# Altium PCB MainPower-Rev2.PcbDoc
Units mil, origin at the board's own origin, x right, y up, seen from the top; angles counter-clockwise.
Board outline 11010.03 x 11010.03 mil, 4 copper layers (Top Layer, Internal Plane 1, Internal Plane 2, Bottom Layer); 112 components, 94 nets, 482 pads, 0 vias.
Unrouted connection lines stored in the file: 312.
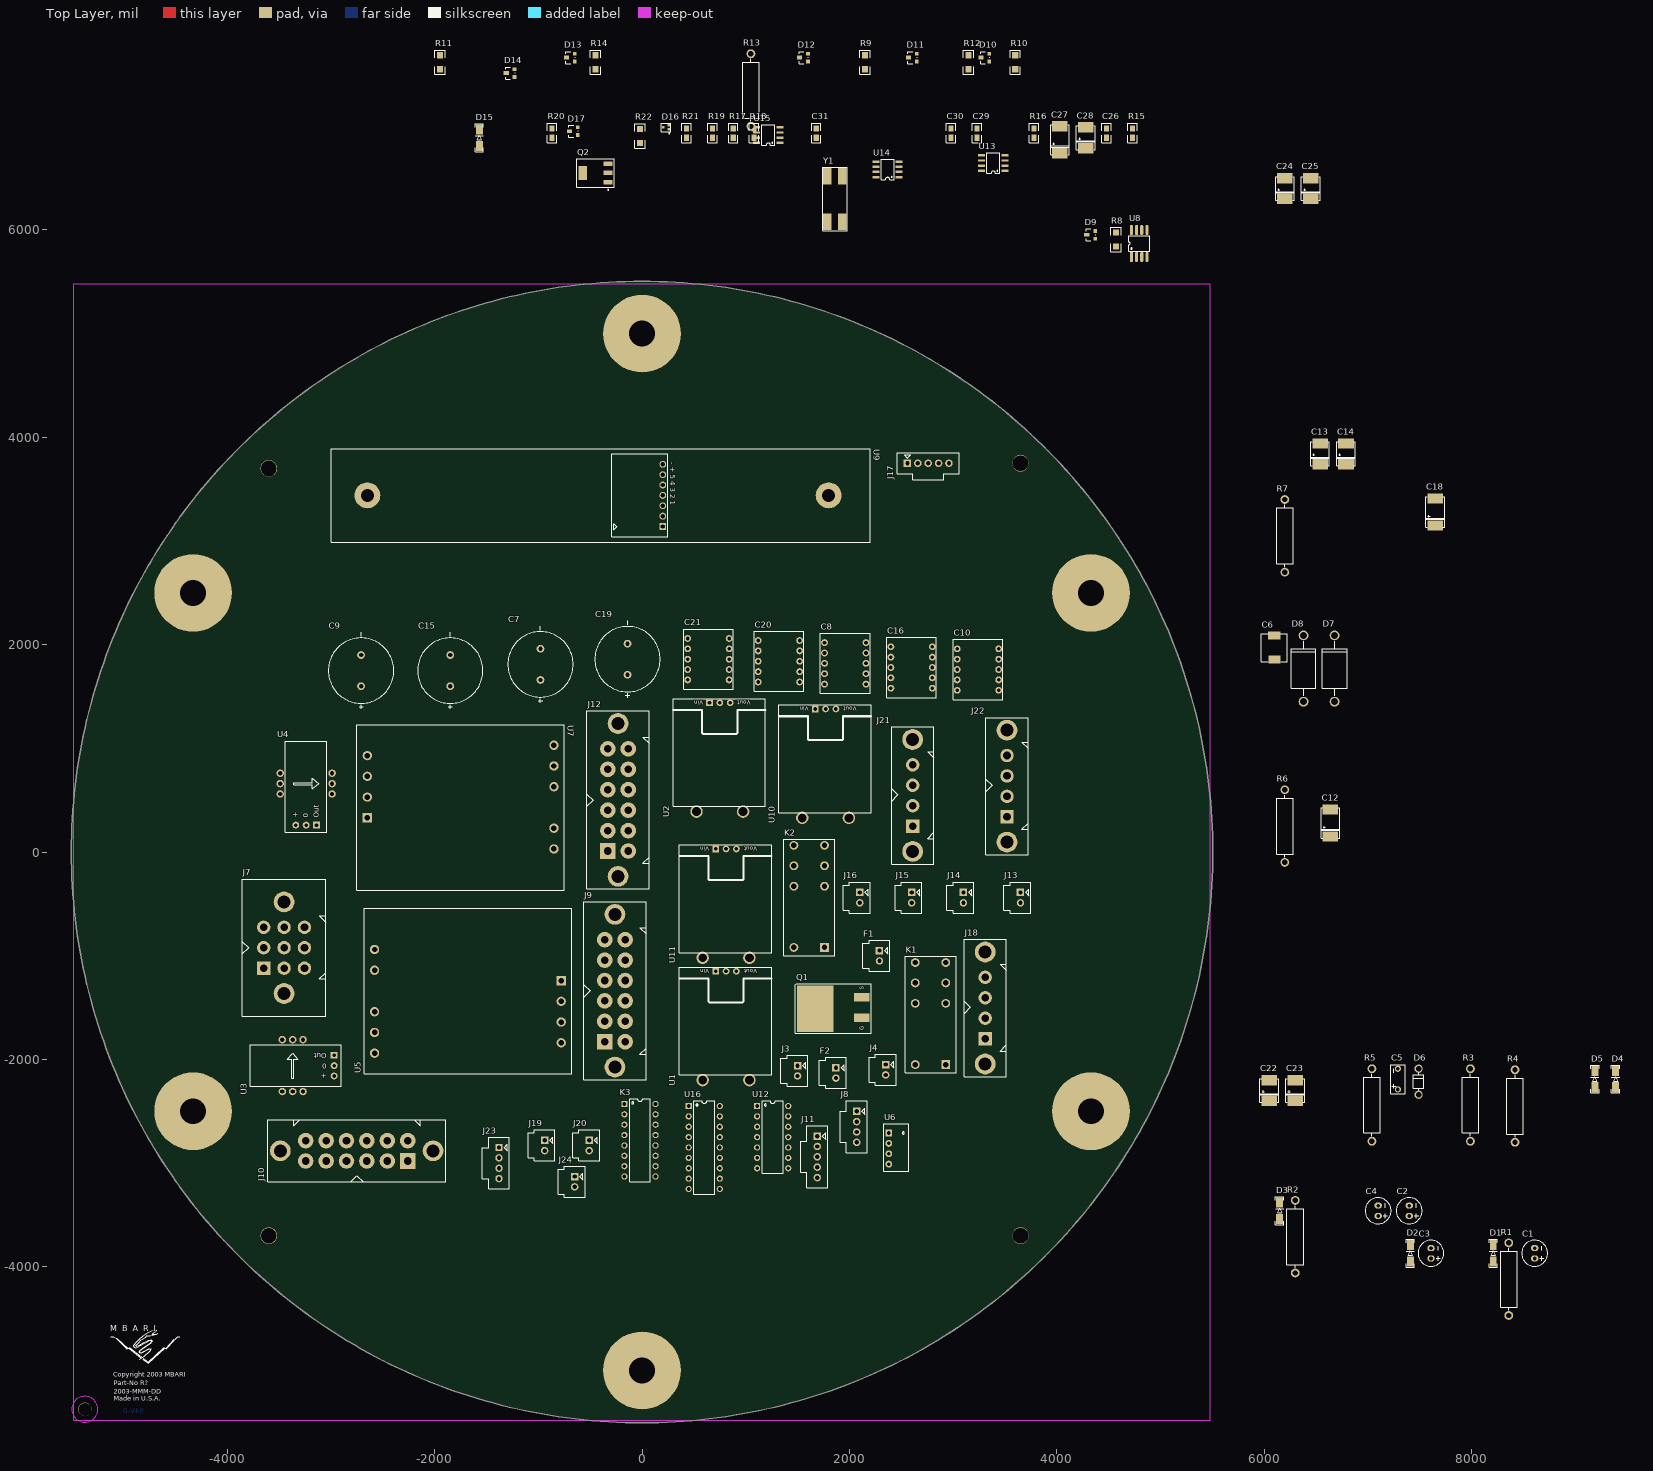
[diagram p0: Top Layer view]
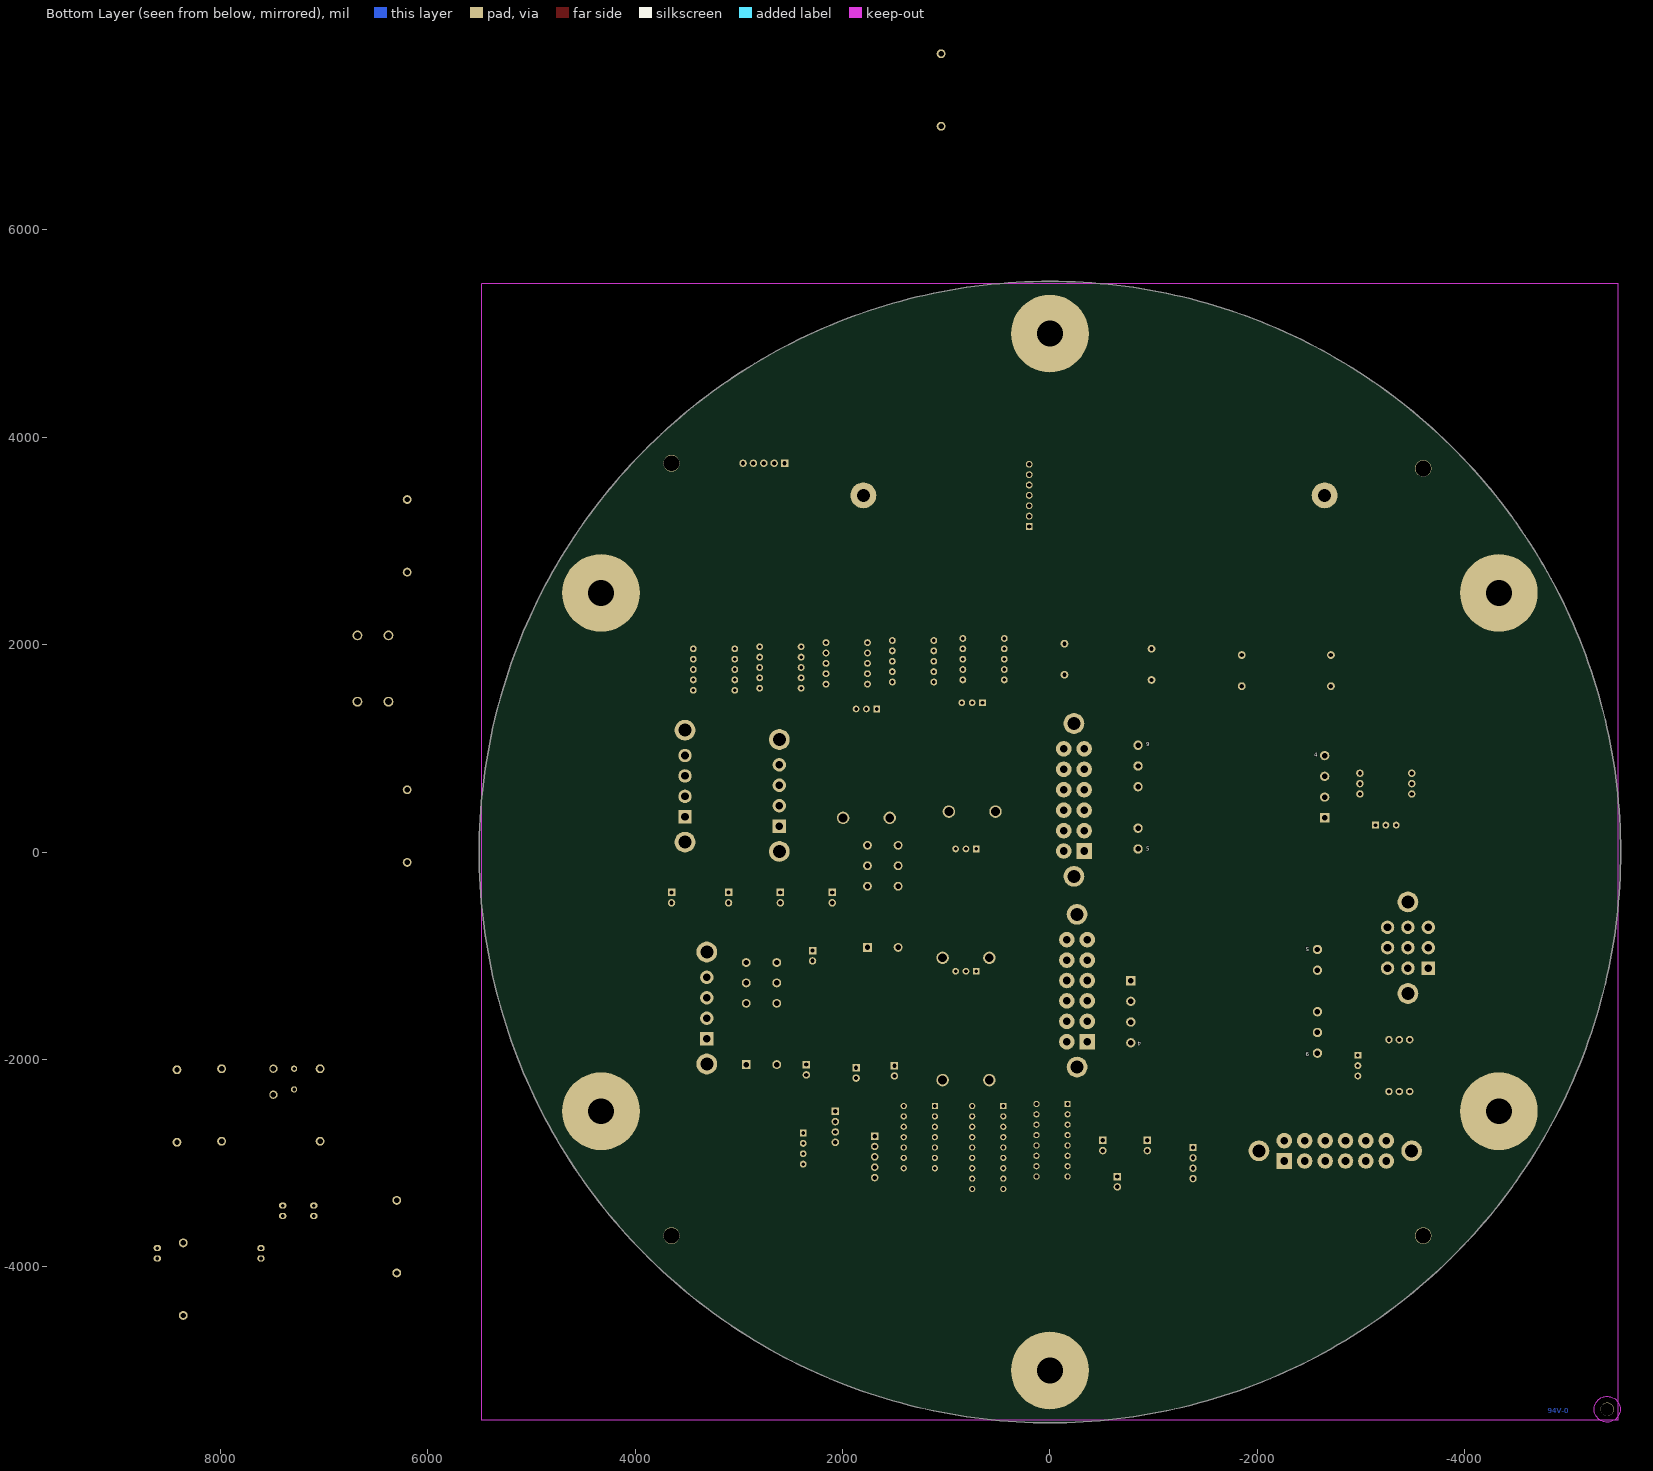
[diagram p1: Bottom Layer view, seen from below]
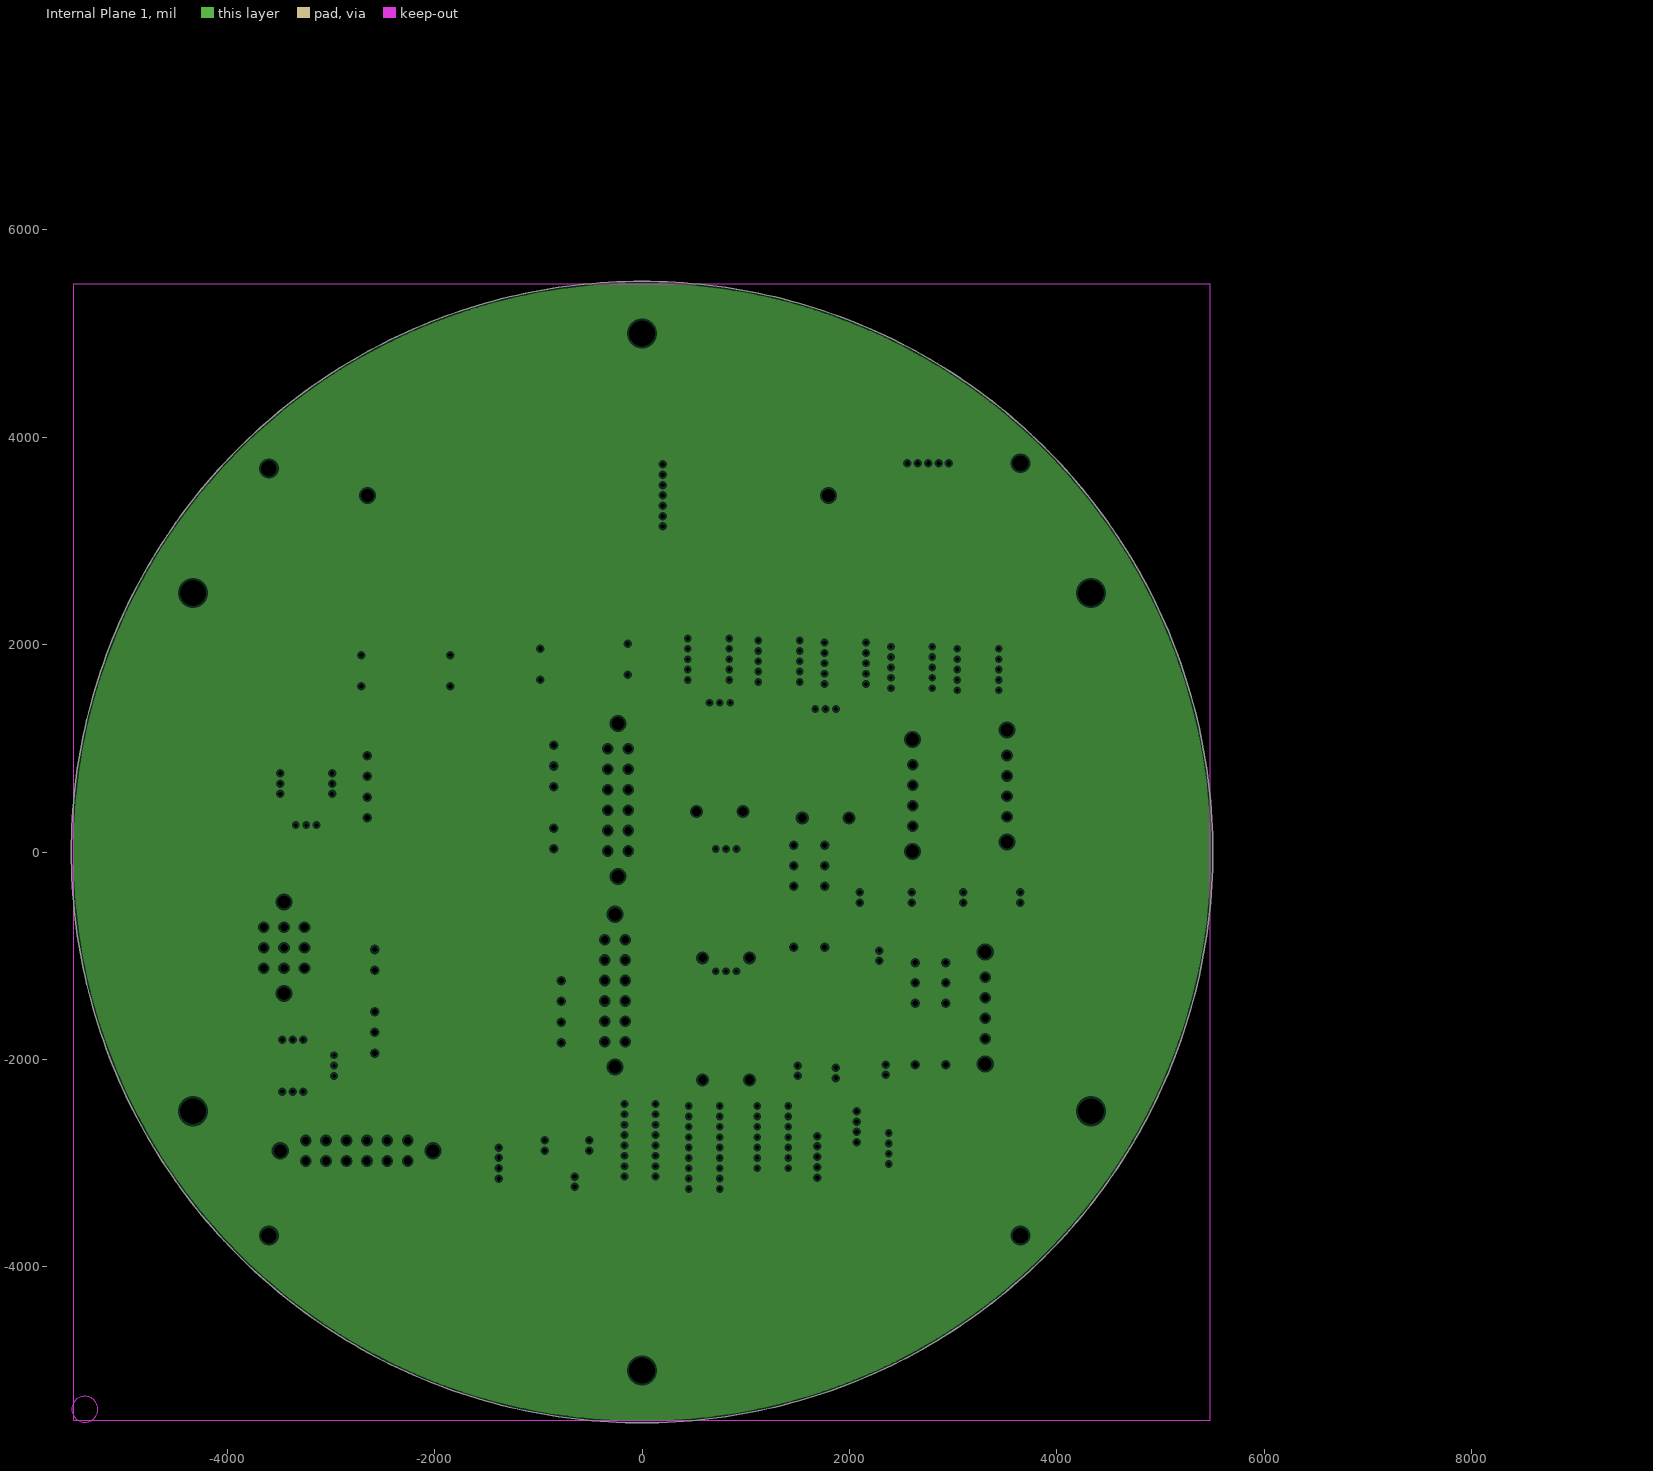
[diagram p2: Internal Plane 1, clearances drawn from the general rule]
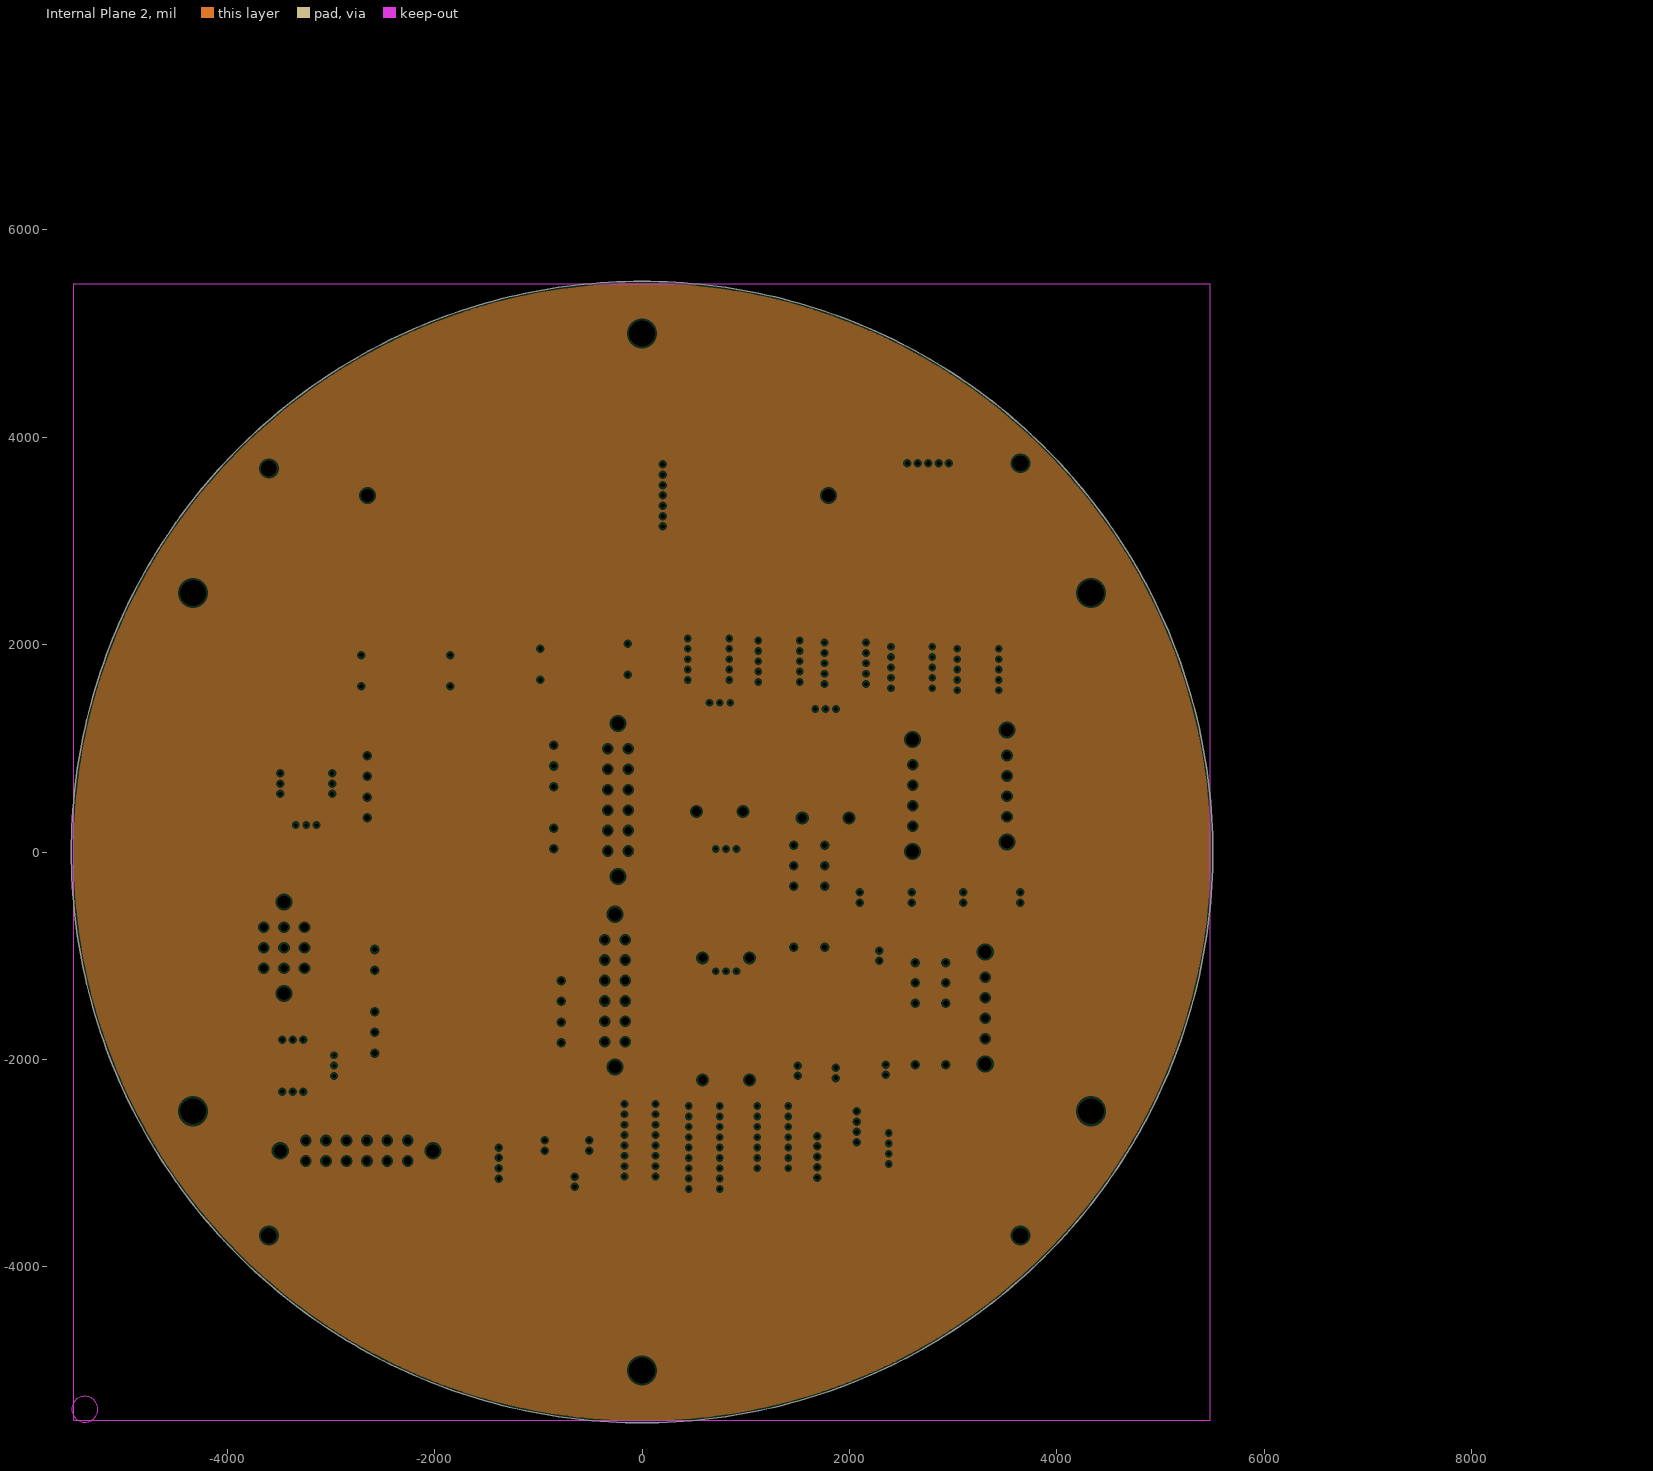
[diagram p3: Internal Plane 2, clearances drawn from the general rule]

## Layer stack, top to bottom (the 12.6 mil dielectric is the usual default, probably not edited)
Top Layer: signal copper 1.4
Dielectric: dielectric 12.6, FR-4, Dk 4.8
Internal Plane 1: plane copper 1.4
Dielectric: dielectric 12.6, FR-4, Dk 4.8
Internal Plane 2: plane copper 1.4
Dielectric: dielectric 12.6, FR-4, Dk 4.8
Bottom Layer: signal copper 1.4

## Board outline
0,-5505.02 cw(c0,0) -5505.02,0 cw(c0,0) 0,5505.01 cw(c0,0) 5505.01,0 cw(c0,0)

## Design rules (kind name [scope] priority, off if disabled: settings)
Clearance [All] p1: gap=13
ComponentClearance [All] p1: gap=10 collisioncheckmode=0
FanoutControl Fanout_Small [(CompPinCount < 5)] p1: bgadir=Out bgaviamode=Centered fanoutstyle=Auto fanoutdirection=OutThenIn viagrid=1 // Fanout_Small (Default Rule)
FanoutControl Fanout_Default [All] p2: bgadir=Out bgaviamode=Centered fanoutstyle=Auto fanoutdirection=Alternating viagrid=1 // Fanout_Default (Default Rule)
FanoutControl Fanout_BGA [IsBGA] p4: bgadir=Out bgaviamode=Centered fanoutstyle=Auto fanoutdirection=Alternating viagrid=1 // Fanout_BGA (Default Rule)
FanoutControl Fanout_LCC [IsLCC] p5: bgadir=Out bgaviamode=Centered fanoutstyle=Auto fanoutdirection=Alternating viagrid=1 // Fanout_LCC (Default Rule)
HoleSize [All] p1: absolutevalues=TRUE maxlimit=152 minlimit=1 maxpercent=80.000 minpercent=20.000
PlaneClearance [All] p1: clearance=20
PlaneConnect [All] p1: planeconnectstyle=Relief reliefexpansion=20 reliefentries=4 reliefconductorwidth=10 reliefairgap=10
PolygonConnect [All] p1: connectstyle=Relief reliefconductorwidth=10 reliefentries=4 polygonreliefangle="90 Angle"
RoutingLayers [All] p1: top layer=Horizontal bottom layer=Vertical
RoutingVias [All] p1: holewidth=35 width=52 viastyle="Through Hole" minholewidth=28 minwidth=32 maxholewidth=86 maxwidth=72
SolderMaskExpansion [All] p1: expansion=4
TestPointUsage [All] p1: valid=0 allowmultiple=FALSE
Testpoint [All] p1: side=15 testpointundercomponent=TRUE minsize=40 maxsize=100 preferedsize=60 minholesize=0 maxholesize=40 preferedholesize=32 testpointgrid=1 style=1023 order=1234567890
Width [All] p1: maxlimit=250 minlimit=8 preferedwidth=12 toplayer_prefwidth=10 bottomlayer_prefwidth=10 minimp=50.000000 maximp=50.000000 favimp=50.000000
9 further rules are at their usual default settings.

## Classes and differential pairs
component class BattBacked-Rev2: C1 C2 C3 C4 C5 D1 D2 D3 D4 D5 D6 F1 F2 J1 J2 J3 J4 J5 J6 K1 K2 Q1 R1 R2 R3 R4 R5 U1 U2
component class GPS: C22 C23 U10
component class ISO5V-25W-MVC-Rev2: C9 C10 C11 C12 R6 U5
component class ISO12V-30W-MVC-Rev2: C15 C16 C17 C18 R7 U7
component class Input-Caps-Diodes-CurrentSensing: C6 C7 C8 D7 D8 U3 U4
component class Iridium: C24 C25 U11
component class MainPower-Rev2: C19 C20 C21 D9 D10 D11 D12 D13 D14 J7 J8 J9 J10 J11 J12 J13 J14 J15 J16 J17 J18 J19 J20 J21 J22 J23 J24 R8 R9 R10 R11 R12 R13 R14 U8 U9
component class "Parosci Iso": C13 C14 U6
component class Watchdog-Rev2: C26 C27 C28 C29 C30 C31 D15 D16 D17 J25 J26 K3 Q2 R15 R16 R17 R18 R19 R20 R21 R22 R23 R24 U12 U13 U14 U15 U16 Y1

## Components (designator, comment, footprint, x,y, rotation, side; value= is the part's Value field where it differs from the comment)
C1 "47uF" RAD0.1L_0.25D 8610,-3920 r90 top
C2 "47uF" RAD0.1L_0.25D 7400,-3510 r90 top
C3 "100uF" RAD0.1L_0.25D 7610,-3920 r90 top
C4 "100uF" RAD0.1L_0.25D 7100,-3510 r90 top
C5 "0.47uF" RAD0.2_POL 7290,-2290 r90 top
C6 "100pF,2kV" ECK 6080,1850 r90 top
C7 "1000uF" RAD0.3L_0.63D -980,1660 r90 top
C8 "10uF" CAPSTICK-CS4-5 1760,1620 r90 top
C9 "1000uF" RAD0.3L_0.63D -2710,1600 r90 top
C10 "10uF" CAPSTICK-CS4-5 3040,1560 r90 top
C12 "150uF" 7343pol 6640,150 r90 top
C13 "33uF" 6032pol 6540,3740 r90 top
C14 "33uF" 6032pol 6790,3740 r90 top
C15 "1000uF" RAD0.3L_0.63D -1850,1600 r90 top
C16 "10uF" CAPSTICK-CS4-5 2400,1580 r90 top
C18 "47uF" 7343pol 7650,3150 r90 top
C19 "1000uF" RAD0.3L_0.63D -140,1710 r90 top
C20 "10uF" CAPSTICK-CS4-5 1120,1640 r90 top
C21 "10uF" CAPSTICK-CS4-5 440,1660 r90 top
C22 "33uF" 6032pol 6050,-2400 r90 top
C23 "100uF" 6032pol 6300,-2400 r90 top
C24 "33uF" 6032pol 6200,6300 r90 top
C25 "100uF" 6032pol 6450,6300 r90 top
C26 "0.001uF" 0805 4480,6890 r90 top
C27 "6.8uF" 7343pol 4030,6740 r90 top
C28 "10uF" 6032pol 4280,6790 r90 top
C29 "0.1uF" 0805 3230,6890 r90 top
C30 "15pF" 0805 2980,6890 r90 top
C31 "15pF" 0805 1680,6890 r90 top
D1 "S1G-13" SMA 8210,-3870 r90 top
D2 "S1G-13" SMA 7410,-3870 r90 top
D3 "S1G-13" SMA 6150,-3460 r90 top
D4 "S1G-13" SMA 9390,-2190 r90 top
D5 "S1G-13" SMA 9190,-2190 r90 top
D6 "1N5245" DIODE0.25 7490,-2340 r90 top
D7 "1N5365B" DO-201AD 6680,1450 r90 top
D8 "1N5401" DO-201AD 6380,1450 r90 top
D9 "5V Blue" SOT-23 4370,5990 r90 top
D10 "12V Yellow" SOT-23 3350,7700 r90 top
D11 "3.3V Green" SOT-23 2650,7700 r90 top
D12 "Irid Blue" SOT-23 1600,7700 r90 top
D13 "Parosci Green" SOT-23 -650,7700 r90 top
D14 "USBL Yellow" SOT-23 -1230,7550 r90 top
D15 "S1G-13" SMA -1570,6890 r90 top
D16 "SDMP0340LCT" SOT-523 230,6990 r90 top
D17 "DW Red" SOT-23 -620,6990 r90 top
F1 "13A Slo-Blo" CGRID2 2290,-950 r90 top
F2 "3A Slo-Blo" CGRID2 1870,-2080 r90 top
J3 "SW-Press" CGRID2 1500,-2060 r90 top
J4 "SW-EmrgEn" CGRID2 2350,-2050 r90 top
J7 "RawBus" PLC09 -3650,-1120 r90 top
J8 "CurSense" CGRID4 2070,-2500 r90 top
J9 "5V Power" PLB12 -360,-1830 r90 top
J10 "RawBusComps" PLB12 -2260,-2980 r180 top
J11 "Temp" CGRID5 1690,-2740 r90 top
J12 "12V Power" PLB12 -330,10 r90 top
J13 "3.3V" CGRID2 3650,-390 r90 top
J14 "3.3V" CGRID2 3100,-390 r90 top
J15 "Iridium" CGRID2 2600,-390 r90 top
J16 "5.0V" CGRID2 2100,-390 r90 top
J17 "StrobeSig" CGRID5 2560,3750 r180 top
J18 "USBL/AComms" PLA04 3310,-1800 r90 top
J19 "PTT" CGRID2 -940,-2780 r90 top
J20 "Strobe" CGRID2 -510,-2780 r90 top
J21 "Parosci/DropW" PLA04 2610,250 r90 top
J22 "BackupBatts" PLA04 3520,340 r90 top
J23 "WatchDog" CGRID4 -1380,-2850 r90 top
J24 "ACommsDropNow" CGRID2 -650,-3130 r90 top
K1 "SPDT 28V" NAIS-LZ 2930,-2050 r90 top
K2 "SPDT 10V" NAIS-LZ 1760,-920 r90 top
K3 "DW DPDT" DIP16 -170,-2430 r0 top
Q1 "IRF3205S" D2PAK 2120,-1600 r90 top
Q2 "IRLL014N" DSO-G3 -450,6550 r90 top
R1 "600" AXIAL0.7 8360,-4470 r90 top
R2 "600" AXIAL0.7 6300,-4060 r90 top
R3 "100K" AXIAL0.7 7990,-2790 r90 top
R4 "100K" AXIAL0.7 8420,-2800 r90 top
R5 "1M" AXIAL0.7 7040,-2790 r90 top
R6 "Rtrim" AXIAL0.7 6200,-100 r90 top
R7 "Rtrim" AXIAL0.7 6200,2700 r90 top
R8 "3.9K" 1206 4570,5840 r90 top
R9 "3.9K" 1206 2150,7550 r90 top
R10 "11K" 1206 3600,7550 r90 top
R11 "11K" 1206 -1950,7550 r90 top
R12 "2.2K" 1206 3150,7550 r90 top
R13 "10K" AXIAL0.7 1050,7000 r90 top
R14 "8.2K" 1206 -450,7550 r90 top
R15 "1M" 0805 4730,6890 r90 top
R16 "1M" 0805 3780,6890 r90 top
R17 "10K" 0805 880,6890 r90 top
R18 "10K" 0805 1080,6890 r90 top
R19 "10K" 0805 680,6890 r90 top
R20 "10K" 0805 -870,6890 r90 top
R21 "1K" 0805 430,6890 r90 top
R22 "26K" 1206 -20,6840 r90 top
U1 "PT78ST112H" PT78ST-HORIZ 810,-1150 r180 top
U2 "PT78ST112H" PT78ST-HORIZ 750,1440 r180 top
U3 "LTS6-NP" LTS6-NP -2900,-2260 r180 top
U4 "LTS6-NP" LTS6-NP -3440,190 r90 top
U5 "UHE-5/5000-Q12" DATEL-UHE -780,-1240 r180 top
U6 "NKE1209S" NKEDCDC 2380,-2710 r0 top
U7 "UHE-12/2500-D24" DATEL-UHE -2650,330 r0 top
U8 "DS1620S" SOIC-8 4720,5740 r90 top
U9 "ST411" ST411 2200,3440 r270 top
U10 "78ST133HC" PT78ST-HORIZ 1770,1380 r180 top
U11 "78HT305HC" PT78ST-HORIZ 810,30 r180 top
U12 "LT1020CN" DIP14 1110,-2450 r0 top
U13 "ADUM1100AR" SO-G8/D5 3500,6570 r90 top
U14 "ADUM1100AR" SO-G8/D5 2480,6510 r90 top
U15 "ADUM1100AR" SO-G8/D5 1330,6840 r90 top
U16 "PIC16F88" DIP18 450,-2450 r0 top
Y1 "4.096MHz" MA-506 1930,6080 r90 top

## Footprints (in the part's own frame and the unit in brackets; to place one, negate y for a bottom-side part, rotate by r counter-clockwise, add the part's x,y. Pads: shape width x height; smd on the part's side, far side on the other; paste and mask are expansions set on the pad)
0805 [mil]
  rect 60x50 smd: 1(0,0) 2(90,0)
  silkscreen extent -50,-45 140,45
1206 [mil]
  rect 60x60 smd: 1(0,0) 2(135,0)
  silkscreen extent -50,-50 185,50
6032pol [mil]
  rect 100x150 smd: 1(0,0) 2(200,0)
  silkscreen extent -15,-90 215,90
7343pol [mil]
  rect 100x150 smd: 1(0,0) 2(260,0)
  silkscreen extent -15,-90 275,90
AXIAL0.7 [mil]
  round 85 hole 52: 1(0,0) 2(700,0)
  silkscreen extent 50,-80 650,80
CAPSTICK-CS4-5 [mil]
  round 66 hole 35: 1(0,0) 1(100,0) 1(200,0) 1(300,0) 1(400,0) 2(0,-400) 2(100,-400) 2(200,-400) 2(300,-400) 2(400,-400)
  silkscreen extent -90,-440 490,40
CGRID2 [mil]
  rect 72x72 hole 42: 1(0,0)
  round 72 hole 42: 2(-100,0)
  silkscreen extent -200,-100 100,160
CGRID4 [mil]
  rect 72x72 hole 42: 1(0,0)
  round 72 hole 42: 2(-100,0) 3(-200,0) 4(-300,0)
  silkscreen extent -400,-100 100,160
CGRID5 [mil]
  rect 72x72 hole 42: 1(0,0)
  round 72 hole 42: 2(-100,0) 3(-200,0) 4(-300,0) 5(-400,0)
  silkscreen extent -500,-100 100,160
D2PAK [mil] "IRF D2Pak SMD-220"
  rect 82x150 smd: 1(0,0) 3(200,0)
  rect 450x350 smd: 2(90,450)
  silkscreen extent -150,-90 330,640
DATEL-UHE [mil] "Datel UHE 1.6x2.0 DC/DC Converter"
  rect 90x90 hole 52: 1(0,0)
  round 90 hole 52: 2(0,200) 3(0,400) 4(0,600) 5(1800,-300) 6(1800,-100) 7(1800,300) 8(1800,500) 9(1800,700)
  silkscreen extent -100,-700 1900,900
DIODE0.25 [mil]
  round 80 hole 52: 1(0,0) 2(250,0)
  silkscreen extent 40,-50 210,50
DIP14 [mil]
  rect 60x60 hole 35: 1(0,0)
  round 60 hole 35: 2(0,-100) 3(0,-200) 4(0,-300) 5(0,-400) 6(0,-500) 7(0,-600) 8(300,-600) 9(300,-500) 10(300,-400) 11(300,-300) 12(300,-200) 13(300,-100) 14(300,0)
  silkscreen extent 50,-650 250,50
DIP16 [mil]
  rect 60x60 hole 35: 1(0,0)
  round 60 hole 35: 2(0,-100) 3(0,-200) 4(0,-300) 5(0,-400) 6(0,-500) 7(0,-600) 8(0,-700) 9(300,-700) 10(300,-600) 11(300,-500) 12(300,-400) 13(300,-300) 14(300,-200) 15(300,-100) 16(300,0)
  silkscreen extent 50,-750 250,50
DIP18 [mil]
  rect 60x60 hole 35: 1(0,0)
  round 60 hole 35: 2(0,-100) 3(0,-200) 4(0,-300) 5(0,-400) 6(0,-500) 7(0,-600) 8(0,-700) 9(0,-800) 10(300,-800) 11(300,-700) 12(300,-600) 13(300,-500) 14(300,-400) 15(300,-300) 16(300,-200) 17(300,-100) 18(300,0)
  silkscreen extent 50,-850 250,50
DO-201AD [mil]
  round 95 hole 67: 1(0,0) 2(640,0)
  silkscreen extent 55,-120 585,120
DSO-G3 [mm]
  rect 1.1x2.15 smd: 1(-2.3,-3.1) 2(0,-3.1) 3(2.3,-3.1)
  rect 3.5x2.15 smd: 4(0,3.1)
  silkscreen extent -4.27,-4.6 3.5,4.6
ECK [mm]
  rect 2x3 smd: 1(0.15,-0.5) 2(6.075,-0.475)
  silkscreen extent -0.4,-3.6 6.5,2.7
LTS6-NP [mil]
  round 72 hole 42: 1(370,-450) 2(470,-450) 3(570,-450) 4(570,50) 5(470,50) 6(370,50)
  rect 66x66 hole 35: a(70,-300)
  round 66 hole 35: b(70,-200) c(70,-100)
  silkscreen extent 0,-400 880,0
MA-506 [mm] "Epson Quartz Crystal"
  rect 4.1x2.1 smd: 1(0,0) 2(11.1,0) 3(11.1,3.6) 4(0,3.6)
  silkscreen extent -2.2,-1.2 13.3,4.8
NAIS-LZ [mil] "NAIS LZ Relay"
  rect 85x85 hole 52: 1(0,0)
  round 85 hole 52: 2(590.55,0) 3(787.4,0) 4(984.25,0) 5(984.25,295.28) 6(787.4,295.28) 7(590.55,295.28) 8(0,295.28)
  silkscreen extent -79,-98 1043,394
NKEDCDC [mil]
  rect 66x66 hole 35: 1(0,0)
  round 66 hole 35: 2(0,-100) 3(0,-200) 4(0,-300)
  silkscreen extent -50,-370 190,90
PLA04 [mil] "Positronic 1x4 pin"
  round 200 hole 125: 0(-244.5,0) 0(835.5,0)
  rect 130x130 hole 73: 1(0,0)
  round 130 hole 73: 2(197,0) 3(394,0) 4(591,0)
  silkscreen extent -366,-204 956,204
PLB12 [mil] "Positronic 2x6 pin"
  round 200 hole 125: 0(-244.5,-98.5) 0(1229.5,-98.5)
  rect 150x150 hole 73: 1(0,0)
  round 150 hole 73: 2(197,0) 3(394,0) 4(591,0) 5(788,0) 6(985,0) 7(0,-197) 8(197,-197) 9(394,-197) 10(591,-197) 11(788,-197) 12(985,-197)
  silkscreen extent -366,-398 1350,202
PLC09 [mil] "Positronic 3x3 pins"
  round 200 hole 125: 0(-244.5,-197) 0(638.5,-197)
  rect 130x130 hole 73: 1(0,0)
  round 130 hole 73: 2(197,0) 3(394,0) 4(0,-197) 5(197,-197) 6(394,-197) 7(0,-394) 8(197,-394) 9(394,-394)
  silkscreen extent -465,-598 859,205
PT78ST-HORIZ [mil]
  round 120 hole 86: 0(-225,1050) 0(225,1050)
  rect 65x65 hole 35: 1(100,0)
  round 65 hole 35: 2(0,0) 3(-100,0)
  silkscreen extent -440,-40 450,1000
RAD0.1L_0.25D [mil]
  oval 60x72 hole 35: 1(0,0) 2(100,0)
  silkscreen extent -75,-125 175,125
RAD0.2_POL [mil] "Polarized Cap"
  round 60 hole 35: 1(0,0) 2(200,0)
  silkscreen extent -40,-70 240,70
RAD0.3L_0.63D [mil]
  round 75 hole 42: 1(0,0) 2(300,0)
  silkscreen extent -220,-315 520,315
SMA [mm] "SMA Diode"
  rect 2.5x1.7 smd: 1(-2,0) 2(2,0)
  silkscreen extent -3.38,-1.02 3.38,1.02
SO-G8/D5 [mm]
  rect 0.6x1.7 smd: 1(0,0) 2(1.27,0) 3(2.54,0) 4(3.81,0) 5(3.81,5.7) 6(2.54,5.7) 7(1.27,5.7) 8(0,5.7)
  silkscreen extent -0.59,1.25 4.4,4.45
SOIC-8 [mil]
  rect 100x30 smd: 1(0,0)
  oval 100x30 smd: 2(0,-50) 3(0,-100) 4(0,-150) 5(260,-150) 6(260,-100) 7(260,-50) 8(260,0)
  silkscreen extent 55,-175 205,25
SOT-23 [mil]
  rect 36x36 smd: 1(0,0) 2(-75,0)
  rect 36x50 smd: 3(-37,80)
  silkscreen extent -95,-5 20,85
SOT-523 [mm] "Diodes Inc SOT-523"
  rect 0.6x0.6 smd: 1(-0.5,-0.7) 2(0.5,-0.7) 3(0,0.7)
  silkscreen extent -1.62,-1.2 1,1.2
ST411 [mil]
  round 250 hole 125: 00(0,-400) 0(0,-4850)
  rect 66x66 hole 42: 1(300,-2000)
  round 66 hole 42: 2(200,-2000) 3(100,-2000) 4(0,-2000) 5(-100,-2000) 6(-200,-2000) 7(-300,-2000)
  silkscreen extent -450,-5200 450,0

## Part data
C1 C2 C3 C4 C5 C7 C9 C13 C14 C15 C19 C22 C23 C24 C25 C27 C28: library part "CAPACITOR POL", "Capacitor"
C6 C8 C10 C16 C20 C21 C26 C29 C30 C31: library part CAPACITOR, "Capacitor"
C12 C18: library part "CAPACITOR POL", "Tantalum Capacitor"
D1 D2 D3 D4 D5 D8 D15: library part DIODE_S, "Diode"
D6 D7: library part ZENER3, "Zener Diode"
D9 D10 D11 D12 D13 D14 D17: library part LED, "LED"
D16: library part DIODE_BARRIER, "Schottky Barrier Diode, Com Cathode"
F1 F2: library part "Fuse 2", "Fuse"
J3 J4 J19 J20: library part CON2, "Connector"
J7: library part CON3X3-PLC, "Positronic 9 pin connector"
J8 J18: library part CON4, "Connector"
J9 J10 J12: library part CON12-PLB-2, "Positronic 12 pin connector"
J11 J17: library part CON5, "Connector"
J13 J14 J15 J16 J24: library part CON2, "Connector C-Grid"
J21 J22: library part CON4-PLA, "Positronic 4 pin connector"
J23: library part CON4, "Connector C-Grid"
K1 K2: library part RELAY-NAIS-LZ-SPDT, "Nais LZ Relay SPDT"
K3: library part RELAY-PB-V23105, "P&B V23105 Relay DPDT"
Q1: library part HEXFET-N, "HexFET"
Q2: "HEXFET Power MOSFET"
R1 R2 R3 R4 R5 R6 R7 R8 R9 R10 R11 R12 R13 R14 R15 R16 R17 R18 R19 R20 R21 R22: library part RESISTOR, "Resistor"
U1 U2 U10: library part PT78STXXX, "Power Trends Switching Reg"
U3 U4: "Current Transducer"
U5 U7: library part UHE, "Datel UHE DC->DC Isolated Converter"
U6: "DC->DC Isol Converter 12->9VDC"
U8: library part DS1620, "DallasSemi Digital Thermometer and Thermostat"
U9: "Novatech Strobe Beacon"
U11: library part PT78STXXX, "Power Trends Switching Reg 5V, 3A"
U12: library part LT1020, "Micropower Regulator"
U13 U14 U15: "Digital Isolator"
U16: "PIC16F88 microcontroller DIP,SOIC package"
Y1: library part XTAL, "Crystal Oscillator"

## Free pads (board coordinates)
  round 130 hole 125: 0(-5375,-5375)
  round 160 hole 152: 0(-3600,-3700) 1(3650,-3700) 2(3650,3750) 3(-3600,3700)
  round 750 hole 250: 0(0,5000) 1(0,-5000) 2(-4330,-2500) 2(-4330,2500) 3(4330,-2500) 3(4330,2500)

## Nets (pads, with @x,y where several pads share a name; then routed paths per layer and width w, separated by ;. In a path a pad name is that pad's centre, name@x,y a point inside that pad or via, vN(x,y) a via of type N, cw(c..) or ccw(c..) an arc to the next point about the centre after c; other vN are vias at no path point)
5V: 
9V: 
9VGND: 
12V: 
AN0VJ3: J8.4 U3.b U4.b
AN5VJ3: J8.1 U3.c U4.c
BUS+: 
BUS-: 
DROPW+: J21.3
DROPW-: J21.4 K3.13
DW5V: C26.1 C28.1 C29.1 R15.1 U12.2 U14.8 U15.1 U15.3 U16.4 U16.14
DW28V: C27.1 D2.2 J4.2 J18.1 K1.3 K3.8 R21.1 U1.1 U12.3
DWGND: C3.2 C27.2 C28.2 C29.2 C30.2 C31.2 D2.1 D14.3 J18.2 J18.3 J24.2 K3.9 Q1.2 Q2.3 R16.2 R17.2 R18.2 R20.1 U1.2 U12.9 U14.5 U14.7 U15.4 U16.5
ELEC+: C1.1 C2.1 C9.1 C10.1 C15.1 C16.1 C19.1 C20.1 C21.1 J10.1 J10.2 J10.3 J10.4 J10.5 J10.6 K1.4 R1.2 R2.2 U2.1 U4.1 U4.2 U4.3 U5.1 U7.1
ELECCUR: J8.3 U4.a
GND: 
IRID5V+: C25.1 J15.1 J16.1 R9.1 U11.3
LOCO+: C7.1 C8.1 J7.3 U3.1 U3.2 U3.3
LOCOCUR: J8.2 U3.a
MVC3.3V+: C23.1 J13.1 J14.1 R12.1 U10.3
MVC5V: J23.1 U14.1 U14.3 U15.8
MVC5V+: C12.1 J9.1 J9.2 J9.4 J9.5 J9.6 R8.1 U5.6
MVC12V+: C13.1 C18.1 C22.1 C24.1 J12.1 J12.2 J12.3 J12.4 J12.5 J12.6 R10.1 U6.2 U7.5 U7.6 U10.1 U11.1
MVCGND: J23.3 R19.2 U14.4 U15.5 U15.7
MVCGND: C12.2 C13.2 C18.2 D9.3 D10.3 J9.7 J9.8 J9.10 J9.11 J9.12 J12.7 J12.8 J12.9 J12.10 J12.11 J12.12 R7.2 U5.7 U6.1 U7.7 U7.8
NetC3_1: C3.1 J18.4 U1.3
NetC4_1: C4.1 K2.4 U2.3
NetC5_1: C5.1 R3.2 R4.1
NetC6_1: C6.1 J7.7 J7.8 J7.9
NetC22_2: C22.2 C23.2 D11.3 J13.2 J14.2 U10.2
NetC24_2: C24.2 C25.2 D12.3 J15.2 J16.2 U11.2
NetC26_2: C26.2 R15.2 R16.1 U12.11
NetC30_1: C30.1 U16.16 Y1.4
NetC31_1: C31.1 U16.15 Y1.1
NetD1_2: D1.2 K1.8 R1.1
NetD3_2: D3.2 K2.8 R2.1
NetD4_2: D4.2 J3.1 J19.1 J20.1
NetD5_1: D5.1 D6.2 Q1.1 R4.2 R5.2
NetD5_2: D5.2 J4.1 R3.1
NetD9_2: D9.2 R8.2
NetD10_2: D10.2 R10.2
NetD11_2: D11.2 R12.2
NetD12_2: D12.2 R9.2
NetD13_2: D13.2 R14.2
NetD14_2: D14.2 R11.2
NetD15_1: D15.1 D17.3 K3.1 Q2.2 Q2.4
NetD15_2: D15.2 K3.16 R21.2 R22.2
NetD16_1: D16.1 U16.17
NetD16_2: D16.2 J24.1 R18.1 U16.1
NetD16_3: D16.3 Q2.1 R20.2
NetD17_2: D17.2 R22.1
NetF1_1: F1.1 J22.1
NetF1_2: F1.2 K1.2
NetF2_1: F2.1 J22.3
NetF2_2: F2.2 K2.2
NetJ1_1: 
NetJ1_2: 
NetJ4_1: 
NetJ4_2: 
NetJ4_3: 
NetJ4_4: 
NetJ4_5: 
NetJ5_1: 
NetJ5_2: 
NetJ7_4: J7.4 J7.5 J7.6
NetJ9_3: J9.3 U5.5
NetJ9_9: J9.9 R6.2 U5.8
NetJ11_1: J11.1 U8.4
NetJ11_2: J11.2 U8.8
NetJ11_3: J11.3 U8.1
NetJ11_4: J11.4 U8.2
NetJ11_5: J11.5 U8.3
NetJ17_1: J17.1 U9.1
NetJ17_2: J17.2 R13.2 U9.2
NetJ17_3: J17.3 U9.3
NetJ17_4: J17.4 R13.1 U9.4
NetJ17_5: J17.5 U9.5
NetJ23_2: J23.2 R19.1 U14.2
NetJ23_4: J23.4 U15.6
NetJ25_1: K3.4
NetJ26_1: 
NetJ26_2: 
NetJ26_3: 
NetJ26_4: 
NetR6_1: R6.1 U5.9
NetR7_1: R7.1 U7.9
NetR17_1: R17.1 U14.6 U16.6
NetU15_2: U15.2 U16.18
PARO9V+: C14.1 J21.1 R14.1 U6.4
PARO9VGND: C14.2 D13.3 J21.2 U6.3
RAWBUS+: D7.2 D8.2 J7.1 J7.2 U3.4 U3.5 U3.6 U4.4 U4.5 U4.6
RAWBUS-: C1.2 C2.2 C4.2 C5.2 C6.2 C7.2 C8.2 C9.2 C10.2 C15.2 C16.2 C19.2 C20.2 C21.2 D1.1 D3.1 D4.1 D6.1 D7.1 D8.1 J10.7 J10.8 J10.9 J10.10 J10.11 J10.12 J19.2 J20.2 J22.2 J22.4 K1.1 K2.1 Q1.3 R5.1 U2.2 U5.2 U7.2
SHIELD: 
SW10VDC: J3.2 K2.3
pads on no net: D9.1 D10.1 D11.1 D12.1 D13.1 D14.1 D17.1 J7.0 J9.0 J10.0 J12.0 J18.0 J21.0 J22.0 K1.5 K1.6 K1.7 K2.5 K2.6 K2.7 K3.2 K3.3 K3.5 K3.6 K3.7 K3.10 K3.11 K3.12 K3.14 K3.15 R11.1 U1.0 U2.0 U5.3 U5.4 U7.3 U7.4 U8.5 U8.6 U8.7 U9.0 U9.00 U9.6 U9.7 U10.0 U11.0 U12.1 U12.4 U12.5 U12.6 U12.7 U12.8 U12.10 U12.12 U12.13 U12.14 U13.1 U13.2 U13.3 U13.4 U13.5 U13.6 U13.7 U13.8 U16.2 U16.3 U16.7 U16.8 U16.9 U16.10 U16.11 U16.12 U16.13 Y1.2 Y1.3

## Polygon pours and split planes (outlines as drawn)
no net on Internal Plane 1 (split plane): 0,-5485 cw(c0,0) -5485,0 cw(c0,0) 0,5485 cw(c0,0) 5485,0 cw(c0,0)
no net on Internal Plane 2 (split plane): 0,-5485 cw(c0,0) -5485,0 cw(c0,0) 0,5485 cw(c0,0) 5485,0 cw(c0,0)

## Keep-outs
Keep-Out Layer:
  circle w10: c-5375,-5375 r125
  lines w10: -5480,-5480 5480,-5480 5480,5480 -5480,5480 -5480,-5480
  text ".GKO" at 12740,-6040 h90

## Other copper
Top Layer:
  text ".GTL" at 12740,-6040 h90
Bottom Layer:
  text "94V-0" at -4802.93,-5411.21 h50
  text ".GBL" at 12740,-6040 h90

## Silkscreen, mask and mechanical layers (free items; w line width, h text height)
Top Overlay:
  lines w10: -5127,-4674 -5095,-4676 -5064,-4694 -4963,-4785 -4950,-4781 -4943,-4782 -4829,-4869 ; -5072,-4692 -4969,-4789 ; -4964,-4792 -4949,-4788 -4834,-4876 ; -4847,-4892 -4801,-4865 -4742,-4811 -4739,-4804 -4739,-4794 -4741,-4791 -4747,-4790 -4754,-4790 ; -4816,-4890 -4769,-4927 ; -4812,-4883 -4764,-4921 -4612,-4783 -4603,-4779 -4589,-4784 -4510,-4698 -4507,-4703 -4478,-4677 -4458,-4673 ; -4740,-4805 -4740,-4797 -4742,-4793 -4747,-4791 -4754,-4790 ; -4606,-4787 -4591,-4792 ; -4584,-4788 -4519,-4715 ; -4516,-4718 -4510,-4709 ; -4754,-4790 -4761,-4793 -4804,-4813 -4821,-4824 -4844,-4828 -4848,-4823 -4847,-4811 -4809,-4779 -4741,-4732 -4730,-4716 -4734,-4705 -4740,-4703 -4764,-4709 -4800,-4729 -4848,-4757 -4878,-4767 -4882,-4763 -4871,-4748 -4853,-4733 -4831,-4703 -4813,-4693 -4798,-4686 -4785,-4678 -4778,-4667 -4743,-4667 -4720,-4662 -4704,-4656 -4688,-4651 -4671,-4641 -4676,-4645 -4705,-4650 -4722,-4650 -4679,-4611 -4728,-4619 -4767,-4637 -4810,-4665 -4849,-4699 -4877,-4726 -4899,-4751 -4903,-4759 -4904,-4765 -4901,-4772 -4896,-4776 -4888,-4781 -4878,-4780 -4750,-4710 -4740,-4707 -4733,-4707 -4729,-4709 -4727,-4713 -4725,-4718 -4728,-4725 -4736,-4734 -4831,-4799 -4842,-4807 -4846,-4815 -4847,-4821 -4843,-4828 -4836,-4830 -4828,-4828 -4754,-4790 ; -4763,-4932 -4604,-4787 -4763,-4932
  text "M  B  A  R  I" at -5130,-4620 h55
  text "Copyright 2003 MBARI" at -5100,-5060 h45
  text "Part-No R?" at -5095,-5143.32 h45
  text "2003-MMM-DD" at -5095,-5223.32 h45
  text "Made in U.S.A." at -5095,-5293.32 h45
  text ".GTO" at 12740,-6040 h90
Bottom Overlay:
  text ".GBO" at 12750,-6040 h90
Top Solder:
  text ".GTS" at 12740,-6040 h90
Bottom Solder:
  text ".GBS" at 12740,-6040 h90
Drill Guide:
  text ".GG1" at 9950,-6040 h90
Mechanical 4:
  circle w10: c-0.27,0 r4550.27
  circle w10: c0,0 r5500
  rectangle: -3890,-3890 3890,3890
  lines w10: -5500,-5500 5500,-5500 5500,5500 -5500,5500 -5500,-5500
Mechanical 16:
  lines w5: -6300,-3700 -6100,-3700 ; -6300,-1300 -6100,-1300 ; -6300,1100 -6100,1100 ; -6300,3500 -6100,3500 ; -6300,5900 -6100,5900 ; -3900,-6300 -3900,-6100 ; -3900,8100 -3900,8300 ; -1500,-6300 -1500,-6100 ; -1500,8100 -1500,8300 ; 900,-6300 900,-6100 ; 900,8100 900,8300 ; 3300,-6300 3300,-6100 ; 3300,8100 3300,8300 ; 5600,-6100 13100,-6100 ; 5700,-6300 5700,-6100 ; 5700,8100 5700,8300 ; 7200,-5500 13100,-5500 ; 8100,-6300 8100,-6100 ; 8100,8100 8100,8300 ; 8600,-5800 13100,-5800 ; 8600,-5200 10100,-5200 ; 10100,-6100 10100,-5500 10100,-4900 ; 10500,-6300 10500,-6100 ; 10500,8100 10500,8300 ; 12200,-6100 12200,-5500 ; 13100,-4900 10100,-4900 ; 13100,-3700 13300,-3700 ; 13100,-1300 13300,-1300 ; 13100,1100 13300,1100 ; 13100,3500 13300,3500 ; 13100,5900 13300,5900 ; 8600,-4900 7200,-4900 7200,-6100 8600,-6100 8600,-4900 ; 8600,-4900 10100,-4900 ; 13100,-6100 -6100,-6100 -6100,8100 13100,8100 13100,-6100 ; -6300,-6300 -6300,8300 13300,8300 13300,-6300 -6300,-6300
  lines w10: 7533,-5054 7565,-5056 7596,-5074 7697,-5165 7710,-5161 7717,-5162 7831,-5249 ; 7588,-5072 7691,-5169 ; 7696,-5172 7711,-5168 7826,-5256 ; 7813,-5272 7859,-5245 7918,-5191 7921,-5184 7921,-5174 7919,-5171 7913,-5170 7906,-5170 ; 7844,-5270 7891,-5307 ; 7848,-5263 7896,-5301 8048,-5163 8057,-5159 8071,-5164 8150,-5078 8153,-5083 8182,-5057 8202,-5053 ; 7920,-5185 7920,-5177 7918,-5173 7913,-5171 7906,-5170 ; 8054,-5167 8069,-5172 ; 8076,-5168 8141,-5095 ; 8144,-5098 8150,-5089 ; 7906,-5170 7899,-5173 7856,-5193 7839,-5204 7816,-5208 7812,-5203 7813,-5191 7851,-5159 7919,-5112 7930,-5096 7926,-5085 7920,-5083 7896,-5089 7860,-5109 7812,-5137 7782,-5147 7778,-5143 7789,-5128 7807,-5113 7829,-5083 7847,-5073 7862,-5066 7875,-5058 7882,-5047 7917,-5047 7940,-5042 7956,-5036 7972,-5031 7989,-5021 7984,-5025 7955,-5030 7938,-5030 7981,-4991 7932,-4999 7893,-5017 7850,-5045 7811,-5079 7783,-5106 7761,-5131 7757,-5139 7756,-5145 7759,-5152 7764,-5156 7772,-5161 7782,-5160 7910,-5090 7920,-5087 7927,-5087 7931,-5089 7933,-5093 7935,-5098 7932,-5105 7924,-5114 7829,-5179 7818,-5187 7814,-5195 7813,-5201 7817,-5208 7824,-5210 7832,-5208 7906,-5170 ; 7897,-5312 8056,-5167 7897,-5312
  text "7" at 9370,8170 h70
  text "8" at 11740,8170 h70
  text "1" at -4980,8160 h70
  text "2" at -2700,8160 h70
  text "3" at -340,8160 h70
  text "4" at 2010,8160 h70
  text "5" at 4470,8160 h70
  text "6" at 6840,8160 h70
  text "A" at -6230,7040 h70
  text "A" at 13170,7040 h70
  text "B" at -6240,4630 h70
  text "B" at 13160,4630 h70
  text "C" at -6220,2360 h70
  text "C" at 13180,2360 h70
  text "D" at -6240,-90 h70
  text "D" at 13160,-90 h70
  text "E" at -6220,-2600 h70
  text "E" at 13180,-2600 h70
  text "M  B  A  R  I" at 7530,-5000 h55
  text "ENGINEER:" at 8650,-5000 h45
  text "TITLE:" at 10150,-5000 h45
  text "Mark Sibenac" at 9160,-5030 h70
  text "F" at -6240,-5050 h70
  text "F" at 13160,-5050 h70
  text "Title I" at 10500,-5120 h90
  text "1 831 775 2028" at 9150,-5170 h60
  text "PCB DESIGNER:" at 8650,-5295 h45
  text "Title II" at 10520,-5340 h90
  text "Copyright      2003" at 7380,-5350 h60
  text "Monterey Bay Aquarium Research Institute" at 7250,-5460 h45
  text "DATE:" at 8650,-5600 h45
  text "PART NO.:" at 10150,-5600 h45
  text "REV:" at 12250,-5600 h45
  text ".PRINT_DATE" at 8700,-5720 h70
  text "1" at 12530,-5720 h90
  text "Part Number" at 10510,-5730 h60
  text "M.B.A.R.I." at 7280,-5740 h100
  text "7700 Sandholdt Rd." at 7270,-5840 h60
  text "FILE NAME:" at 8650,-5900 h45
  text "DWG NO:" at 10150,-5900 h45
  text "GERBER:" at 12250,-5900 h45
  text "Moss Landing, CA 95039" at 7270,-5950 h60
  text "DWG Number" at 10510,-5990 h60
  text ".PCB_FILE_NAME_NO_PATH" at 8700,-6020 h70
  text ".GM16" at 12360,-6030 h70
  text "Fax: 1 831 775 1646" at 7270,-6050 h60
  text "7" at 9370,-6230 h70
  text "8" at 11740,-6230 h70
  text "1" at -4980,-6240 h70
  text "2" at -2700,-6240 h70
  text "3" at -340,-6240 h70
  text "4" at 2010,-6240 h70
  text "5" at 4470,-6240 h70
  text "6" at 6840,-6240 h70
Drill Drawing:
  text ".LEGEND" at 4445,-4630 h60
  text "Drill Drawing." at 4425,-4720 h60
  text ".GD1" at 9945,-6040 h90

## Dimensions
-5500,-5500 to 5500,-5500 on Mechanical 4
-5500,5500 to -5500,-5500 on Mechanical 4
-5375,-5375 to -5500,-5500 on Mechanical 4
-5375,-5375 to -5500,-5500 on Mechanical 4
